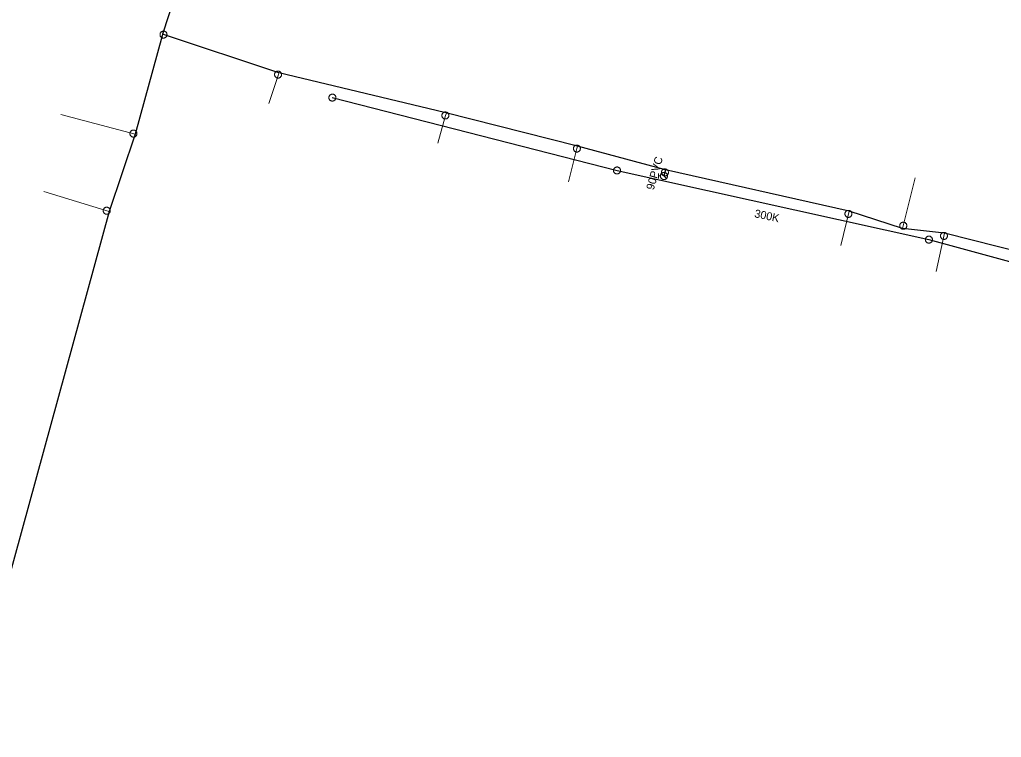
# Model space of a CAD drawing. Extents: x -741806 to -738704, y -1059275 to -1055387.
# Drawn here: x -740293.4 to -740170.7, y -1056910.8 to -1056821.1 of the extents above; entities that cross this region are included whole.
import ezdxf

# ---------------------------------------------------------------- set-up
doc = ezdxf.new("R2010")
doc.units = 0
doc.header["$LTSCALE"] = 0.4
for name, color, linetype, lineweight in [('2', 7, 'Continuous', 25), ('21', 7, 'Continuous', 13), ('3', 7, 'Continuous', 13), ('50', 7, 'Continuous', 13), ('51', 7, 'Continuous', 13), ('52', 7, 'Continuous', 25)]:
    doc.layers.add(name, color=color, linetype=linetype, lineweight=lineweight)
doc.layers.add('5', color=7, linetype='Continuous')
doc.layers.add('53', color=7, linetype='Continuous')

msp = doc.modelspace()

# ---------------------------------------------------------------- linework, layer by layer
at = {"layer": '2'}
msp.add_lwpolyline([(-740254.32, -1056830.86), (-740218.739, -1056839.96), (-740179.76, -1056848.6), (-740146.01, -1056857.78), (-740138.59, -1056847.639)], dxfattribs=at)
at = {"layer": '21'}
for p, q in [((-740278.978, -1056835.415), (-740288.243, -1056832.98)), ((-740183.054, -1056847.2), (-740181.473, -1056840.899)), ((-740282.21, -1056845.104), (-740290.397, -1056842.578)), ((-740189.741, -1056845.049), (-740190.787, -1056849.345)), ((-740177.82, -1056847.787), (-740178.864, -1056852.575))]:
    msp.add_line(p, q, dxfattribs=at)
for points in [[(-740261.017, -1056827.78), (-740261.087, -1056828.107), (-740262.267, -1056831.584)], [(-740240.07, -1056832.792), (-740240.195, -1056833.094), (-740241.153, -1056836.551)], [(-740223.669, -1056836.908), (-740223.754, -1056837.227), (-740224.82, -1056841.397)]]:
    msp.add_lwpolyline(points, dxfattribs=at)
at = {"layer": '3'}
for points in [[(-740253.895, -1056830.969), (-740253.887, -1056830.924), (-740253.883, -1056830.879), (-740253.883, -1056830.832), (-740253.888, -1056830.788), (-740253.898, -1056830.743), (-740253.913, -1056830.699), (-740253.932, -1056830.658), (-740253.955, -1056830.618), (-740253.983, -1056830.582), (-740254.014, -1056830.548), (-740254.048, -1056830.518), (-740254.086, -1056830.49), (-740254.126, -1056830.469), (-740254.167, -1056830.45), (-740254.211, -1056830.437), (-740254.256, -1056830.427), (-740254.302, -1056830.424), (-740254.347, -1056830.424), (-740254.393, -1056830.429), (-740254.438, -1056830.44), (-740254.481, -1056830.454), (-740254.522, -1056830.473), (-740254.562, -1056830.497), (-740254.599, -1056830.523), (-740254.633, -1056830.555), (-740254.662, -1056830.59), (-740254.689, -1056830.626), (-740254.712, -1056830.667), (-740254.73, -1056830.709), (-740254.743, -1056830.753), (-740254.752, -1056830.797), (-740254.757, -1056830.842), (-740254.756, -1056830.889), (-740254.751, -1056830.935), (-740254.741, -1056830.978), (-740254.727, -1056831.022), (-740254.707, -1056831.063), (-740254.683, -1056831.103), (-740254.656, -1056831.139), (-740254.626, -1056831.173), (-740254.591, -1056831.203), (-740254.554, -1056831.231), (-740254.514, -1056831.253), (-740254.472, -1056831.271), (-740254.428, -1056831.284), (-740254.383, -1056831.294), (-740254.338, -1056831.298), (-740254.292, -1056831.297), (-740254.246, -1056831.292), (-740254.201, -1056831.281), (-740254.158, -1056831.267), (-740254.117, -1056831.248), (-740254.077, -1056831.224), (-740254.041, -1056831.198), (-740254.007, -1056831.166), (-740253.976, -1056831.132), (-740253.95, -1056831.095), (-740253.928, -1056831.054), (-740253.91, -1056831.012), (-740253.896, -1056830.969)], [(-740218.314, -1056840.069), (-740218.306, -1056840.024), (-740218.302, -1056839.979), (-740218.302, -1056839.932), (-740218.307, -1056839.888), (-740218.317, -1056839.843), (-740218.332, -1056839.799), (-740218.351, -1056839.758), (-740218.374, -1056839.718), (-740218.402, -1056839.682), (-740218.433, -1056839.648), (-740218.467, -1056839.618), (-740218.505, -1056839.59), (-740218.545, -1056839.569), (-740218.586, -1056839.55), (-740218.63, -1056839.537), (-740218.675, -1056839.527), (-740218.721, -1056839.524), (-740218.766, -1056839.524), (-740218.812, -1056839.529), (-740218.857, -1056839.54), (-740218.9, -1056839.554), (-740218.941, -1056839.573), (-740218.981, -1056839.597), (-740219.018, -1056839.623), (-740219.052, -1056839.655), (-740219.081, -1056839.69), (-740219.108, -1056839.726), (-740219.131, -1056839.767), (-740219.149, -1056839.809), (-740219.162, -1056839.853), (-740219.171, -1056839.897), (-740219.176, -1056839.942), (-740219.175, -1056839.989), (-740219.17, -1056840.035), (-740219.16, -1056840.078), (-740219.146, -1056840.122), (-740219.126, -1056840.163), (-740219.102, -1056840.203), (-740219.075, -1056840.239), (-740219.045, -1056840.273), (-740219.01, -1056840.303), (-740218.973, -1056840.331), (-740218.933, -1056840.353), (-740218.891, -1056840.371), (-740218.847, -1056840.384), (-740218.802, -1056840.394), (-740218.757, -1056840.398), (-740218.711, -1056840.397), (-740218.665, -1056840.392), (-740218.62, -1056840.381), (-740218.577, -1056840.367), (-740218.536, -1056840.348), (-740218.496, -1056840.324), (-740218.46, -1056840.298), (-740218.426, -1056840.266), (-740218.395, -1056840.232), (-740218.369, -1056840.195), (-740218.347, -1056840.154), (-740218.329, -1056840.112), (-740218.315, -1056840.069)], [(-740179.332, -1056848.695), (-740179.325, -1056848.65), (-740179.322, -1056848.605), (-740179.324, -1056848.558), (-740179.331, -1056848.514), (-740179.342, -1056848.469), (-740179.358, -1056848.426), (-740179.379, -1056848.385), (-740179.403, -1056848.346), (-740179.432, -1056848.311), (-740179.464, -1056848.278), (-740179.499, -1056848.249), (-740179.538, -1056848.223), (-740179.578, -1056848.203), (-740179.621, -1056848.185), (-740179.665, -1056848.173), (-740179.71, -1056848.165), (-740179.756, -1056848.163), (-740179.801, -1056848.165), (-740179.847, -1056848.172), (-740179.892, -1056848.184), (-740179.934, -1056848.2), (-740179.974, -1056848.22), (-740180.014, -1056848.245), (-740180.05, -1056848.272), (-740180.082, -1056848.305), (-740180.111, -1056848.341), (-740180.137, -1056848.378), (-740180.158, -1056848.42), (-740180.175, -1056848.462), (-740180.186, -1056848.506), (-740180.194, -1056848.551), (-740180.197, -1056848.596), (-740180.195, -1056848.643), (-740180.188, -1056848.688), (-740180.177, -1056848.732), (-740180.161, -1056848.775), (-740180.14, -1056848.816), (-740180.115, -1056848.855), (-740180.087, -1056848.89), (-740180.055, -1056848.923), (-740180.02, -1056848.952), (-740179.982, -1056848.978), (-740179.941, -1056848.999), (-740179.899, -1056849.016), (-740179.854, -1056849.028), (-740179.809, -1056849.036), (-740179.764, -1056849.039), (-740179.718, -1056849.036), (-740179.672, -1056849.029), (-740179.628, -1056849.017), (-740179.585, -1056849.001), (-740179.544, -1056848.982), (-740179.506, -1056848.956), (-740179.47, -1056848.928), (-740179.437, -1056848.896), (-740179.408, -1056848.86), (-740179.383, -1056848.823), (-740179.361, -1056848.781), (-740179.345, -1056848.739), (-740179.332, -1056848.696)]]:
    msp.add_lwpolyline(points, dxfattribs=at)
at = {"layer": '50'}
for p, q in [((-740213.572, -1056840.342), (-740213.572, -1056840.649)), ((-740213.321, -1056840.649), (-740213.572, -1056840.649)), ((-740213.572, -1056840.957), (-740213.572, -1056840.649)), ((-740212.874, -1056840.649), (-740213.186, -1056840.333)), ((-740212.874, -1056840.649), (-740212.557, -1056840.966))]:
    msp.add_line(p, q, dxfattribs=at)
msp.add_lwpolyline([(-740212.87, -1056840.205), (-740212.919, -1056840.207), (-740212.965, -1056840.212), (-740213.011, -1056840.225), (-740213.054, -1056840.242), (-740213.094, -1056840.261), (-740213.135, -1056840.288), (-740213.17, -1056840.317), (-740213.205, -1056840.35), (-740213.235, -1056840.385), (-740213.259, -1056840.425), (-740213.281, -1056840.466), (-740213.3, -1056840.509), (-740213.31, -1056840.555), (-740213.318, -1056840.601), (-740213.321, -1056840.647), (-740213.318, -1056840.693), (-740213.313, -1056840.738), (-740213.3, -1056840.784), (-740213.283, -1056840.828), (-740213.262, -1056840.871), (-740213.237, -1056840.909), (-740213.208, -1056840.946), (-740213.175, -1056840.979), (-740213.14, -1056841.008), (-740213.1, -1056841.035), (-740213.059, -1056841.057), (-740213.016, -1056841.073), (-740212.97, -1056841.087), (-740212.924, -1056841.092), (-740212.878, -1056841.098), (-740212.83, -1056841.096), (-740212.784, -1056841.088), (-740212.741, -1056841.077), (-740212.695, -1056841.061), (-740212.654, -1056841.039), (-740212.614, -1056841.015), (-740212.579, -1056840.985), (-740212.544, -1056840.953), (-740212.514, -1056840.915), (-740212.49, -1056840.877), (-740212.468, -1056840.834), (-740212.452, -1056840.791), (-740212.438, -1056840.748), (-740212.43, -1056840.699), (-740212.427, -1056840.653), (-740212.43, -1056840.607), (-740212.438, -1056840.561), (-740212.449, -1056840.515), (-740212.465, -1056840.472), (-740212.487, -1056840.429), (-740212.511, -1056840.391), (-740212.541, -1056840.353), (-740212.573, -1056840.321), (-740212.608, -1056840.291), (-740212.649, -1056840.267), (-740212.689, -1056840.243), (-740212.733, -1056840.226), (-740212.778, -1056840.216), (-740212.824, -1056840.208)], close=True, dxfattribs=at)
at = {"layer": '51'}
for points in [[(-740275.42, -1056822.553), (-740275.465, -1056822.554), (-740275.51, -1056822.561), (-740275.555, -1056822.573), (-740275.597, -1056822.589), (-740275.638, -1056822.61), (-740275.677, -1056822.635), (-740275.712, -1056822.664), (-740275.745, -1056822.696), (-740275.773, -1056822.732), (-740275.798, -1056822.77), (-740275.819, -1056822.811), (-740275.836, -1056822.854), (-740275.848, -1056822.898), (-740275.855, -1056822.943), (-740275.857, -1056822.989), (-740275.855, -1056823.035), (-740275.848, -1056823.08), (-740275.836, -1056823.124), (-740275.819, -1056823.167), (-740275.798, -1056823.208), (-740275.773, -1056823.246), (-740275.745, -1056823.282), (-740275.712, -1056823.314), (-740275.677, -1056823.343), (-740275.638, -1056823.368), (-740275.597, -1056823.389), (-740275.555, -1056823.405), (-740275.51, -1056823.417), (-740275.465, -1056823.424), (-740275.419, -1056823.428), (-740275.374, -1056823.425), (-740275.329, -1056823.418), (-740275.284, -1056823.406), (-740275.242, -1056823.39), (-740275.201, -1056823.369), (-740275.162, -1056823.344), (-740275.127, -1056823.315), (-740275.094, -1056823.283), (-740275.066, -1056823.247), (-740275.041, -1056823.209), (-740275.02, -1056823.168), (-740275.003, -1056823.125), (-740274.992, -1056823.081), (-740274.984, -1056823.036), (-740274.982, -1056822.99), (-740274.984, -1056822.944), (-740274.992, -1056822.899), (-740275.003, -1056822.855), (-740275.02, -1056822.812), (-740275.041, -1056822.771), (-740275.066, -1056822.733), (-740275.094, -1056822.697), (-740275.127, -1056822.665), (-740275.162, -1056822.636), (-740275.201, -1056822.611), (-740275.242, -1056822.59), (-740275.284, -1056822.574), (-740275.329, -1056822.562), (-740275.374, -1056822.555), (-740275.419, -1056822.553)], [(-740261.108, -1056827.549), (-740261.153, -1056827.55), (-740261.198, -1056827.557), (-740261.243, -1056827.569), (-740261.285, -1056827.585), (-740261.326, -1056827.606), (-740261.365, -1056827.631), (-740261.4, -1056827.66), (-740261.433, -1056827.692), (-740261.461, -1056827.728), (-740261.486, -1056827.766), (-740261.507, -1056827.807), (-740261.524, -1056827.85), (-740261.536, -1056827.894), (-740261.543, -1056827.939), (-740261.545, -1056827.985), (-740261.543, -1056828.031), (-740261.536, -1056828.076), (-740261.524, -1056828.12), (-740261.507, -1056828.163), (-740261.486, -1056828.204), (-740261.461, -1056828.242), (-740261.433, -1056828.278), (-740261.4, -1056828.31), (-740261.365, -1056828.339), (-740261.326, -1056828.364), (-740261.285, -1056828.385), (-740261.243, -1056828.401), (-740261.198, -1056828.413), (-740261.153, -1056828.42), (-740261.107, -1056828.424), (-740261.062, -1056828.421), (-740261.017, -1056828.414), (-740260.972, -1056828.402), (-740260.93, -1056828.386), (-740260.889, -1056828.365), (-740260.85, -1056828.34), (-740260.815, -1056828.311), (-740260.782, -1056828.279), (-740260.754, -1056828.243), (-740260.729, -1056828.205), (-740260.708, -1056828.164), (-740260.691, -1056828.121), (-740260.68, -1056828.077), (-740260.672, -1056828.032), (-740260.67, -1056827.986), (-740260.672, -1056827.94), (-740260.68, -1056827.895), (-740260.691, -1056827.851), (-740260.708, -1056827.808), (-740260.729, -1056827.767), (-740260.754, -1056827.729), (-740260.782, -1056827.693), (-740260.815, -1056827.661), (-740260.85, -1056827.632), (-740260.889, -1056827.607), (-740260.93, -1056827.586), (-740260.972, -1056827.57), (-740261.017, -1056827.558), (-740261.062, -1056827.551), (-740261.107, -1056827.549)], [(-740240.194, -1056832.657), (-740240.239, -1056832.658), (-740240.284, -1056832.665), (-740240.329, -1056832.677), (-740240.371, -1056832.693), (-740240.412, -1056832.714), (-740240.451, -1056832.739), (-740240.486, -1056832.768), (-740240.519, -1056832.8), (-740240.547, -1056832.836), (-740240.572, -1056832.874), (-740240.593, -1056832.915), (-740240.61, -1056832.958), (-740240.622, -1056833.002), (-740240.629, -1056833.047), (-740240.631, -1056833.093), (-740240.629, -1056833.139), (-740240.622, -1056833.184), (-740240.61, -1056833.228), (-740240.593, -1056833.271), (-740240.572, -1056833.312), (-740240.547, -1056833.35), (-740240.519, -1056833.386), (-740240.486, -1056833.418), (-740240.451, -1056833.447), (-740240.412, -1056833.472), (-740240.371, -1056833.493), (-740240.329, -1056833.509), (-740240.284, -1056833.521), (-740240.239, -1056833.528), (-740240.193, -1056833.532), (-740240.148, -1056833.529), (-740240.103, -1056833.522), (-740240.058, -1056833.51), (-740240.016, -1056833.494), (-740239.975, -1056833.473), (-740239.936, -1056833.448), (-740239.901, -1056833.419), (-740239.868, -1056833.387), (-740239.84, -1056833.351), (-740239.815, -1056833.313), (-740239.794, -1056833.272), (-740239.777, -1056833.229), (-740239.766, -1056833.185), (-740239.758, -1056833.14), (-740239.756, -1056833.094), (-740239.758, -1056833.048), (-740239.766, -1056833.003), (-740239.777, -1056832.959), (-740239.794, -1056832.916), (-740239.815, -1056832.875), (-740239.84, -1056832.837), (-740239.868, -1056832.801), (-740239.901, -1056832.769), (-740239.936, -1056832.74), (-740239.975, -1056832.715), (-740240.016, -1056832.694), (-740240.058, -1056832.678), (-740240.103, -1056832.666), (-740240.148, -1056832.659), (-740240.193, -1056832.657)], [(-740279.602, -1056835.243), (-740279.612, -1056835.287), (-740279.616, -1056835.332), (-740279.616, -1056835.379), (-740279.611, -1056835.424), (-740279.601, -1056835.469), (-740279.587, -1056835.513), (-740279.568, -1056835.554), (-740279.545, -1056835.594), (-740279.518, -1056835.63), (-740279.487, -1056835.664), (-740279.453, -1056835.695), (-740279.416, -1056835.722), (-740279.376, -1056835.745), (-740279.334, -1056835.763), (-740279.29, -1056835.777), (-740279.245, -1056835.786), (-740279.2, -1056835.791), (-740279.155, -1056835.791), (-740279.109, -1056835.785), (-740279.064, -1056835.775), (-740279.021, -1056835.761), (-740278.979, -1056835.743), (-740278.939, -1056835.719), (-740278.902, -1056835.693), (-740278.868, -1056835.661), (-740278.837, -1056835.627), (-740278.811, -1056835.59), (-740278.788, -1056835.55), (-740278.77, -1056835.508), (-740278.756, -1056835.464), (-740278.747, -1056835.42), (-740278.742, -1056835.375), (-740278.742, -1056835.328), (-740278.747, -1056835.284), (-740278.757, -1056835.239), (-740278.771, -1056835.194), (-740278.791, -1056835.153), (-740278.813, -1056835.113), (-740278.841, -1056835.077), (-740278.871, -1056835.043), (-740278.906, -1056835.012), (-740278.943, -1056834.985), (-740278.983, -1056834.963), (-740279.024, -1056834.944), (-740279.068, -1056834.93), (-740279.113, -1056834.921), (-740279.159, -1056834.917), (-740279.204, -1056834.916), (-740279.25, -1056834.922), (-740279.295, -1056834.932), (-740279.338, -1056834.946), (-740279.38, -1056834.964), (-740279.419, -1056834.988), (-740279.456, -1056835.015), (-740279.49, -1056835.046), (-740279.521, -1056835.08), (-740279.547, -1056835.117), (-740279.57, -1056835.157), (-740279.588, -1056835.199), (-740279.602, -1056835.242)], [(-740223.753, -1056836.79), (-740223.798, -1056836.791), (-740223.843, -1056836.798), (-740223.888, -1056836.81), (-740223.93, -1056836.826), (-740223.971, -1056836.847), (-740224.01, -1056836.872), (-740224.045, -1056836.901), (-740224.078, -1056836.933), (-740224.106, -1056836.969), (-740224.131, -1056837.007), (-740224.152, -1056837.048), (-740224.169, -1056837.091), (-740224.181, -1056837.135), (-740224.188, -1056837.18), (-740224.19, -1056837.226), (-740224.188, -1056837.272), (-740224.181, -1056837.317), (-740224.169, -1056837.361), (-740224.152, -1056837.404), (-740224.131, -1056837.445), (-740224.106, -1056837.483), (-740224.078, -1056837.519), (-740224.045, -1056837.551), (-740224.01, -1056837.58), (-740223.971, -1056837.605), (-740223.93, -1056837.626), (-740223.888, -1056837.642), (-740223.843, -1056837.654), (-740223.798, -1056837.661), (-740223.752, -1056837.665), (-740223.707, -1056837.662), (-740223.662, -1056837.655), (-740223.617, -1056837.643), (-740223.575, -1056837.627), (-740223.534, -1056837.606), (-740223.495, -1056837.581), (-740223.46, -1056837.552), (-740223.427, -1056837.52), (-740223.399, -1056837.484), (-740223.374, -1056837.446), (-740223.353, -1056837.405), (-740223.336, -1056837.362), (-740223.325, -1056837.318), (-740223.317, -1056837.273), (-740223.315, -1056837.227), (-740223.317, -1056837.181), (-740223.325, -1056837.136), (-740223.336, -1056837.092), (-740223.353, -1056837.049), (-740223.374, -1056837.008), (-740223.399, -1056836.97), (-740223.427, -1056836.934), (-740223.46, -1056836.902), (-740223.495, -1056836.873), (-740223.534, -1056836.848), (-740223.575, -1056836.827), (-740223.617, -1056836.811), (-740223.662, -1056836.799), (-740223.707, -1056836.792), (-740223.752, -1056836.79)], [(-740212.753, -1056839.766), (-740212.798, -1056839.767), (-740212.843, -1056839.774), (-740212.888, -1056839.786), (-740212.93, -1056839.802), (-740212.971, -1056839.823), (-740213.01, -1056839.848), (-740213.045, -1056839.877), (-740213.078, -1056839.909), (-740213.106, -1056839.945), (-740213.131, -1056839.983), (-740213.152, -1056840.024), (-740213.169, -1056840.067), (-740213.181, -1056840.111), (-740213.188, -1056840.156), (-740213.19, -1056840.202), (-740213.188, -1056840.248), (-740213.181, -1056840.293), (-740213.169, -1056840.337), (-740213.152, -1056840.38), (-740213.131, -1056840.421), (-740213.106, -1056840.459), (-740213.078, -1056840.495), (-740213.045, -1056840.527), (-740213.01, -1056840.556), (-740212.971, -1056840.581), (-740212.93, -1056840.602), (-740212.888, -1056840.618), (-740212.843, -1056840.63), (-740212.798, -1056840.637), (-740212.752, -1056840.641), (-740212.707, -1056840.638), (-740212.662, -1056840.631), (-740212.617, -1056840.619), (-740212.575, -1056840.603), (-740212.534, -1056840.582), (-740212.495, -1056840.557), (-740212.46, -1056840.528), (-740212.427, -1056840.496), (-740212.399, -1056840.46), (-740212.374, -1056840.422), (-740212.353, -1056840.381), (-740212.336, -1056840.338), (-740212.325, -1056840.294), (-740212.317, -1056840.249), (-740212.315, -1056840.203), (-740212.317, -1056840.157), (-740212.325, -1056840.112), (-740212.336, -1056840.068), (-740212.353, -1056840.025), (-740212.374, -1056839.984), (-740212.399, -1056839.946), (-740212.427, -1056839.91), (-740212.46, -1056839.878), (-740212.495, -1056839.849), (-740212.534, -1056839.824), (-740212.575, -1056839.803), (-740212.617, -1056839.787), (-740212.662, -1056839.775), (-740212.707, -1056839.768), (-740212.752, -1056839.766)], [(-740282.938, -1056844.862), (-740282.949, -1056844.906), (-740282.956, -1056844.951), (-740282.958, -1056844.997), (-740282.955, -1056845.042), (-740282.947, -1056845.088), (-740282.934, -1056845.132), (-740282.917, -1056845.174), (-740282.896, -1056845.215), (-740282.87, -1056845.253), (-740282.841, -1056845.288), (-740282.808, -1056845.32), (-740282.772, -1056845.349), (-740282.733, -1056845.373), (-740282.693, -1056845.393), (-740282.649, -1056845.409), (-740282.605, -1056845.42), (-740282.56, -1056845.427), (-740282.514, -1056845.428), (-740282.468, -1056845.425), (-740282.423, -1056845.417), (-740282.379, -1056845.404), (-740282.336, -1056845.388), (-740282.296, -1056845.366), (-740282.258, -1056845.341), (-740282.222, -1056845.311), (-740282.19, -1056845.278), (-740282.163, -1056845.243), (-740282.138, -1056845.203), (-740282.118, -1056845.162), (-740282.102, -1056845.119), (-740282.091, -1056845.075), (-740282.085, -1056845.03), (-740282.083, -1056844.984), (-740282.086, -1056844.939), (-740282.094, -1056844.893), (-740282.106, -1056844.849), (-740282.123, -1056844.807), (-740282.144, -1056844.766), (-740282.17, -1056844.729), (-740282.199, -1056844.693), (-740282.232, -1056844.661), (-740282.268, -1056844.632), (-740282.307, -1056844.609), (-740282.348, -1056844.588), (-740282.391, -1056844.572), (-740282.436, -1056844.561), (-740282.481, -1056844.555), (-740282.526, -1056844.553), (-740282.573, -1056844.556), (-740282.618, -1056844.564), (-740282.662, -1056844.577), (-740282.704, -1056844.593), (-740282.745, -1056844.615), (-740282.783, -1056844.64), (-740282.818, -1056844.67), (-740282.85, -1056844.703), (-740282.878, -1056844.738), (-740282.902, -1056844.778), (-740282.922, -1056844.819), (-740282.938, -1056844.861)], [(-740189.821, -1056844.944), (-740189.866, -1056844.945), (-740189.911, -1056844.952), (-740189.956, -1056844.964), (-740189.998, -1056844.98), (-740190.039, -1056845.001), (-740190.078, -1056845.026), (-740190.113, -1056845.055), (-740190.146, -1056845.087), (-740190.174, -1056845.123), (-740190.199, -1056845.161), (-740190.22, -1056845.202), (-740190.237, -1056845.245), (-740190.249, -1056845.289), (-740190.256, -1056845.334), (-740190.258, -1056845.38), (-740190.256, -1056845.426), (-740190.249, -1056845.471), (-740190.237, -1056845.515), (-740190.22, -1056845.558), (-740190.199, -1056845.599), (-740190.174, -1056845.637), (-740190.146, -1056845.673), (-740190.113, -1056845.705), (-740190.078, -1056845.734), (-740190.039, -1056845.759), (-740189.998, -1056845.78), (-740189.956, -1056845.796), (-740189.911, -1056845.808), (-740189.866, -1056845.815), (-740189.82, -1056845.819), (-740189.775, -1056845.816), (-740189.73, -1056845.809), (-740189.685, -1056845.797), (-740189.643, -1056845.781), (-740189.602, -1056845.76), (-740189.563, -1056845.735), (-740189.528, -1056845.706), (-740189.495, -1056845.674), (-740189.467, -1056845.638), (-740189.442, -1056845.6), (-740189.421, -1056845.559), (-740189.404, -1056845.516), (-740189.393, -1056845.472), (-740189.385, -1056845.427), (-740189.383, -1056845.381), (-740189.385, -1056845.335), (-740189.393, -1056845.29), (-740189.404, -1056845.246), (-740189.421, -1056845.203), (-740189.442, -1056845.162), (-740189.467, -1056845.124), (-740189.495, -1056845.088), (-740189.528, -1056845.056), (-740189.563, -1056845.027), (-740189.602, -1056845.002), (-740189.643, -1056844.981), (-740189.685, -1056844.965), (-740189.73, -1056844.953), (-740189.775, -1056844.946), (-740189.82, -1056844.944)], [(-740182.957, -1056846.421), (-740183.002, -1056846.422), (-740183.047, -1056846.429), (-740183.092, -1056846.441), (-740183.134, -1056846.457), (-740183.175, -1056846.478), (-740183.214, -1056846.503), (-740183.249, -1056846.532), (-740183.282, -1056846.564), (-740183.31, -1056846.6), (-740183.335, -1056846.638), (-740183.356, -1056846.679), (-740183.373, -1056846.722), (-740183.385, -1056846.766), (-740183.392, -1056846.811), (-740183.394, -1056846.857), (-740183.392, -1056846.903), (-740183.385, -1056846.948), (-740183.373, -1056846.992), (-740183.356, -1056847.035), (-740183.335, -1056847.076), (-740183.31, -1056847.114), (-740183.282, -1056847.15), (-740183.249, -1056847.182), (-740183.214, -1056847.211), (-740183.175, -1056847.236), (-740183.134, -1056847.257), (-740183.092, -1056847.273), (-740183.047, -1056847.285), (-740183.002, -1056847.292), (-740182.956, -1056847.296), (-740182.911, -1056847.293), (-740182.866, -1056847.286), (-740182.821, -1056847.274), (-740182.779, -1056847.258), (-740182.738, -1056847.237), (-740182.699, -1056847.212), (-740182.664, -1056847.183), (-740182.631, -1056847.151), (-740182.603, -1056847.115), (-740182.578, -1056847.077), (-740182.557, -1056847.036), (-740182.54, -1056846.993), (-740182.529, -1056846.949), (-740182.521, -1056846.904), (-740182.519, -1056846.858), (-740182.521, -1056846.812), (-740182.529, -1056846.767), (-740182.54, -1056846.723), (-740182.557, -1056846.68), (-740182.578, -1056846.639), (-740182.603, -1056846.601), (-740182.631, -1056846.565), (-740182.664, -1056846.533), (-740182.699, -1056846.504), (-740182.738, -1056846.479), (-740182.779, -1056846.458), (-740182.821, -1056846.442), (-740182.866, -1056846.43), (-740182.911, -1056846.423), (-740182.956, -1056846.421)], [(-740177.874, -1056847.692), (-740177.919, -1056847.693), (-740177.964, -1056847.7), (-740178.009, -1056847.712), (-740178.051, -1056847.728), (-740178.092, -1056847.749), (-740178.131, -1056847.774), (-740178.166, -1056847.803), (-740178.199, -1056847.835), (-740178.227, -1056847.871), (-740178.252, -1056847.909), (-740178.273, -1056847.95), (-740178.29, -1056847.993), (-740178.302, -1056848.037), (-740178.309, -1056848.082), (-740178.311, -1056848.128), (-740178.309, -1056848.174), (-740178.302, -1056848.219), (-740178.29, -1056848.263), (-740178.273, -1056848.306), (-740178.252, -1056848.347), (-740178.227, -1056848.385), (-740178.199, -1056848.421), (-740178.166, -1056848.453), (-740178.131, -1056848.482), (-740178.092, -1056848.507), (-740178.051, -1056848.528), (-740178.009, -1056848.544), (-740177.964, -1056848.556), (-740177.919, -1056848.563), (-740177.873, -1056848.567), (-740177.828, -1056848.564), (-740177.783, -1056848.557), (-740177.738, -1056848.545), (-740177.696, -1056848.529), (-740177.655, -1056848.508), (-740177.616, -1056848.483), (-740177.581, -1056848.454), (-740177.548, -1056848.422), (-740177.52, -1056848.386), (-740177.495, -1056848.348), (-740177.474, -1056848.307), (-740177.457, -1056848.264), (-740177.446, -1056848.22), (-740177.438, -1056848.175), (-740177.436, -1056848.129), (-740177.438, -1056848.083), (-740177.446, -1056848.038), (-740177.457, -1056847.994), (-740177.474, -1056847.951), (-740177.495, -1056847.91), (-740177.52, -1056847.872), (-740177.548, -1056847.836), (-740177.581, -1056847.804), (-740177.616, -1056847.775), (-740177.655, -1056847.75), (-740177.696, -1056847.729), (-740177.738, -1056847.713), (-740177.783, -1056847.701), (-740177.828, -1056847.694), (-740177.873, -1056847.692)]]:
    msp.add_lwpolyline(points, dxfattribs=at)
at = {"layer": '52'}
msp.add_line((-740212.664, -1056839.887), (-740212.879, -1056840.649), dxfattribs=at)
for points in [[(-740175.489, -1056516.148), (-740182.237, -1056558.509), (-740182.283, -1056558.799), (-740184.208, -1056574.021), (-740186.954, -1056588.264), (-740195.633, -1056638.315), (-740197.478, -1056649.388), (-740200.254, -1056663.476), (-740207.839, -1056691.395), (-740209.772, -1056694), (-740210.063, -1056694.828), (-740213.269, -1056698.987), (-740231.234, -1056717.463), (-740244.285, -1056733.611), (-740248.473, -1056741.574), (-740255.759, -1056760.318), (-740256.949, -1056764.72), (-740259.395, -1056771.79), (-740264.607, -1056786.706), (-740265.408, -1056790.486), (-740270.787, -1056807.514), (-740272.432, -1056813.382), (-740275.537, -1056822.95), (-740275.601, -1056823.152)], [(-740275.601, -1056823.152), (-740278.978, -1056835.415), (-740282.21, -1056845.104), (-740296.842, -1056898.301), (-740316.568, -1056963.017)], [(-740136.706, -1056857.977), (-740154.291, -1056853.747), (-740177.82, -1056847.787), (-740183.054, -1056847.2), (-740189.741, -1056845.049), (-740212.664, -1056839.887), (-740223.669, -1056836.908), (-740240.309, -1056832.732), (-740261.017, -1056827.78), (-740275.537, -1056822.95)]]:
    msp.add_lwpolyline(points, dxfattribs=at)

# ---------------------------------------------------------------- texts
at = {"layer": '5'}
msp.add_text('300K', height=1, rotation=348, dxfattribs=at).set_placement((-740201.631, -1056845.785))
at = {"layer": '53'}
msp.add_text('90PVC ', height=1, rotation=74, dxfattribs=at).set_placement((-740214.157, -1056842.474))

doc.saveas('drawing.dxf')
